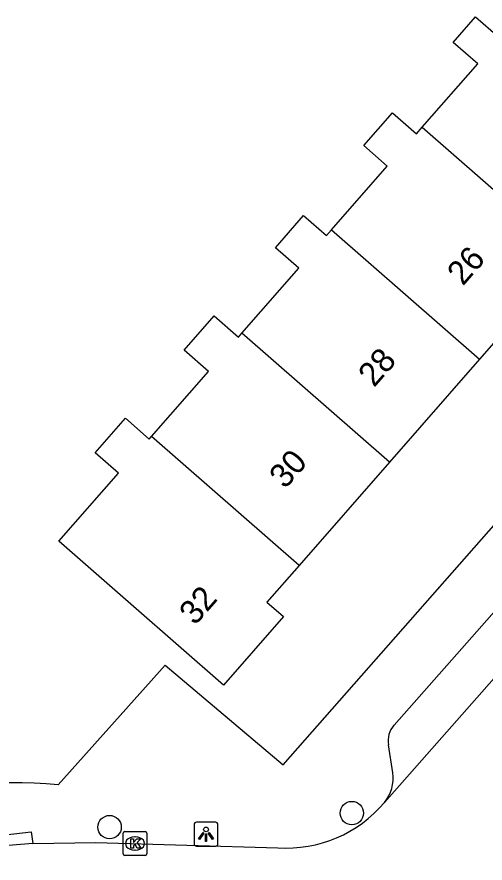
# Model space of a CAD drawing. Extents: x 158474 to 159560, y 388525 to 389605.
# Drawn here: x 158838.92 to 158858.47, y 388942.99 to 388978.37 of the extents above; entities that cross this region are included whole.
import ezdxf

# ---------------------------------------------------------------- set-up
doc = ezdxf.new("R2010")
doc.units = 0
for name, color, linetype in [('IMGEO_Boom', 7, 'Continuous'), ('IMGEO_Kolk', 7, 'Continuous'), ('IMGEO_Lichtpunt', 7, 'Continuous'), ('IMGEO_Pand', 7, 'Continuous'), ('IMGEO_Pand_nummerreeks', 7, 'Continuous'), ('IMGEO_Rijbaan_lokaal_open', 7, 'Continuous'), ('IMGEO_Voetpad_open', 7, 'Continuous')]:
    doc.layers.add(name, color=color, linetype=linetype)

msp = doc.modelspace()

# ---------------------------------------------------------------- linework, layer by layer
at = {"layer": 'IMGEO_Boom'}
for centre in [(158852.903, 388945.084), (158842.786, 388944.497)]:
    msp.add_circle(centre, 0.489, dxfattribs=at)
at = {"layer": 'IMGEO_Kolk'}
for p, q in [((158843.346, 388943.386), (158843.346, 388944.238)), ((158843.421, 388944.312), (158844.273, 388944.312)), ((158843.834, 388944.092), (158843.859, 388944.092)), ((158844.347, 388944.238), (158844.347, 388943.386)), ((158844.273, 388943.312), (158843.421, 388943.312)), ((158843.857, 388943.532), (158843.832, 388943.532))]:
    msp.add_line(p, q, dxfattribs=at)
for points in [[(158843.346, 388943.386), (158843.346, 388944.238)], [(158843.421, 388944.312), (158844.273, 388944.312)], [(158843.667, 388944.012), (158843.79, 388944.012), (158843.79, 388943.861), (158843.92, 388944.012), (158844.084, 388944.012), (158843.938, 388943.861), (158844.091, 388943.612), (158843.939, 388943.612), (158843.854, 388943.776), (158843.79, 388943.709), (158843.79, 388943.612), (158843.667, 388943.612), (158843.667, 388944.012)], [(158844.347, 388944.238), (158844.347, 388943.386)], [(158844.273, 388943.312), (158843.421, 388943.312)]]:
    msp.add_lwpolyline(points, dxfattribs=at)
for centre, start, end in [((158843.423, 388944.236), 91.552, 178.448), ((158843.423, 388944.236), 91.552, 178.448), ((158844.271, 388944.236), 1.552, 88.448), ((158844.271, 388944.236), 1.552, 88.448), ((158843.423, 388943.388), 181.552, 268.448), ((158843.423, 388943.388), 181.552, 268.448), ((158844.271, 388943.388), 271.552, 358.448), ((158844.271, 388943.388), 271.552, 358.448)]:
    msp.add_arc(centre, 0.0765, start, end, dxfattribs=at)
for centre, major_axis, ratio, start_param, end_param in [((158843.833, 388943.812), (-0.387, 0.002), 0.722429, 4.712389, 7.853982), ((158843.858, 388943.812), (-0.39, 0.002), 0.717154, 1.570796, 4.712389)]:
    msp.add_ellipse(centre, major_axis=major_axis, ratio=ratio, start_param=start_param, end_param=end_param, dxfattribs=at)
at = {"layer": 'IMGEO_Lichtpunt'}
for p, q in [((158847.217, 388944.699), (158846.409, 388944.699)), ((158847.217, 388944.699), (158846.409, 388944.699)), ((158846.315, 388944.604), (158846.315, 388943.797)), ((158846.315, 388944.604), (158846.315, 388943.797)), ((158847.311, 388943.797), (158847.311, 388944.604)), ((158847.311, 388943.797), (158847.311, 388944.604)), ((158846.409, 388943.703), (158847.217, 388943.703)), ((158846.409, 388943.703), (158847.217, 388943.703))]:
    msp.add_line(p, q, dxfattribs=at)
for points in [[(158846.689, 388944.268), (158846.728, 388944.24), (158846.54, 388943.978), (158846.502, 388944.005), (158846.689, 388944.268)], [(158846.791, 388944.22), (158846.838, 388944.22), (158846.838, 388943.898), (158846.791, 388943.898), (158846.791, 388944.22)], [(158846.901, 388944.24), (158846.939, 388944.267), (158847.126, 388944.005), (158847.087, 388943.977), (158846.901, 388944.24)]]:
    msp.add_lwpolyline(points, dxfattribs=at)
msp.add_circle((158846.814, 388944.402), 0.0994, dxfattribs=at)
for centre, start, end in [((158846.409, 388944.604), 90, 180), ((158846.409, 388944.604), 90, 180), ((158847.217, 388944.604), 0, 90), ((158847.217, 388944.604), 0, 90), ((158846.409, 388943.797), 180, 270), ((158846.409, 388943.797), 180, 270), ((158847.217, 388943.797), 270, 0), ((158847.217, 388943.797), 270, 360)]:
    msp.add_arc(centre, 0.0946, start, end, dxfattribs=at)
at = {"layer": 'IMGEO_Pand'}
for points in [[(158855.844, 388973.765), (158858.161, 388976.415), (158857.142, 388977.306), (158858.075, 388978.373), (158859.025, 388977.542), (158859.322, 388977.883), (158860.865, 388976.534), (158861.086, 388976.786)], [(158852.057, 388969.469), (158854.386, 388972.133), (158853.404, 388972.991), (158854.599, 388974.358), (158855.598, 388973.484), (158855.844, 388973.765)], [(158855.844, 388973.765), (158862.008, 388968.374)], [(158848.305, 388965.145), (158850.685, 388967.867), (158849.709, 388968.72), (158850.891, 388970.072), (158851.851, 388969.233), (158852.057, 388969.469)], [(158852.057, 388969.469), (158858.239, 388964.062)], [(158862.008, 388968.374), (158858.239, 388964.062)], [(158844.536, 388960.834), (158846.914, 388963.553), (158845.9, 388964.439), (158847.152, 388965.871), (158848.165, 388964.985), (158848.305, 388965.145)], [(158854.47, 388959.752), (158848.305, 388965.145)], [(158858.239, 388964.062), (158854.47, 388959.752)], [(158850.701, 388955.442), (158849.357, 388953.904), (158850.051, 388953.297), (158847.547, 388950.433), (158843.783, 388953.724), (158840.667, 388956.448), (158843.157, 388959.296), (158842.185, 388960.146), (158843.448, 388961.59), (158844.439, 388960.723), (158844.536, 388960.834)], [(158850.701, 388955.442), (158844.536, 388960.834)], [(158854.47, 388959.752), (158850.701, 388955.442)]]:
    msp.add_lwpolyline(points, dxfattribs=at)
at = {"layer": 'IMGEO_Rijbaan_lokaal_open'}
for points in [[(158871.145, 388964.681), (158854.263, 388945.529)], [(158839.577, 388943.809), (158836.852, 388943.584)], [(158839.577, 388943.809), (158842.212, 388943.859), (158849.816, 388943.633)]]:
    msp.add_lwpolyline(points, dxfattribs=at)
msp.add_arc((158850.184, 388948.933), 5.312, 266.0264, 320.156, dxfattribs=at)
at = {"layer": 'IMGEO_Voetpad_open'}
for points in [[(158854.665, 388948.76), (158872.03, 388968.46)], [(158840.636, 388946.266), (158845.102, 388951.266), (158850.029, 388947.103), (158868.044, 388967.58)], [(158854.621, 388946.77), (158854.429, 388947.936)], [(158834.368, 388943.201), (158834.305, 388943.696), (158839.514, 388944.304), (158839.577, 388943.809)]]:
    msp.add_lwpolyline(points, dxfattribs=at)
for centre, radius, start, end in [((158855.424, 388948.097), 1.008, 138.867, 189.1688), ((158853.015, 388946.561), 1.619, 320.4062, 7.4105), ((158838.86, 388929.017), 17.34, 84.1197, 136.4831)]:
    msp.add_arc(centre, radius, start, end, dxfattribs=at)

# ---------------------------------------------------------------- texts
at = {"layer": 'IMGEO_Pand_nummerreeks'}
for s, rotation, p in [('26', 48.8349, (158857.546, 388967.099)), ('28', 48.8349, (158853.834, 388962.853)), ('30', 48.8349, (158850.119, 388958.605)), ('32', 48.8367, (158846.357, 388952.899))]:
    msp.add_text(s, height=1, rotation=rotation, dxfattribs=at).set_placement(p)

doc.saveas('drawing.dxf')
